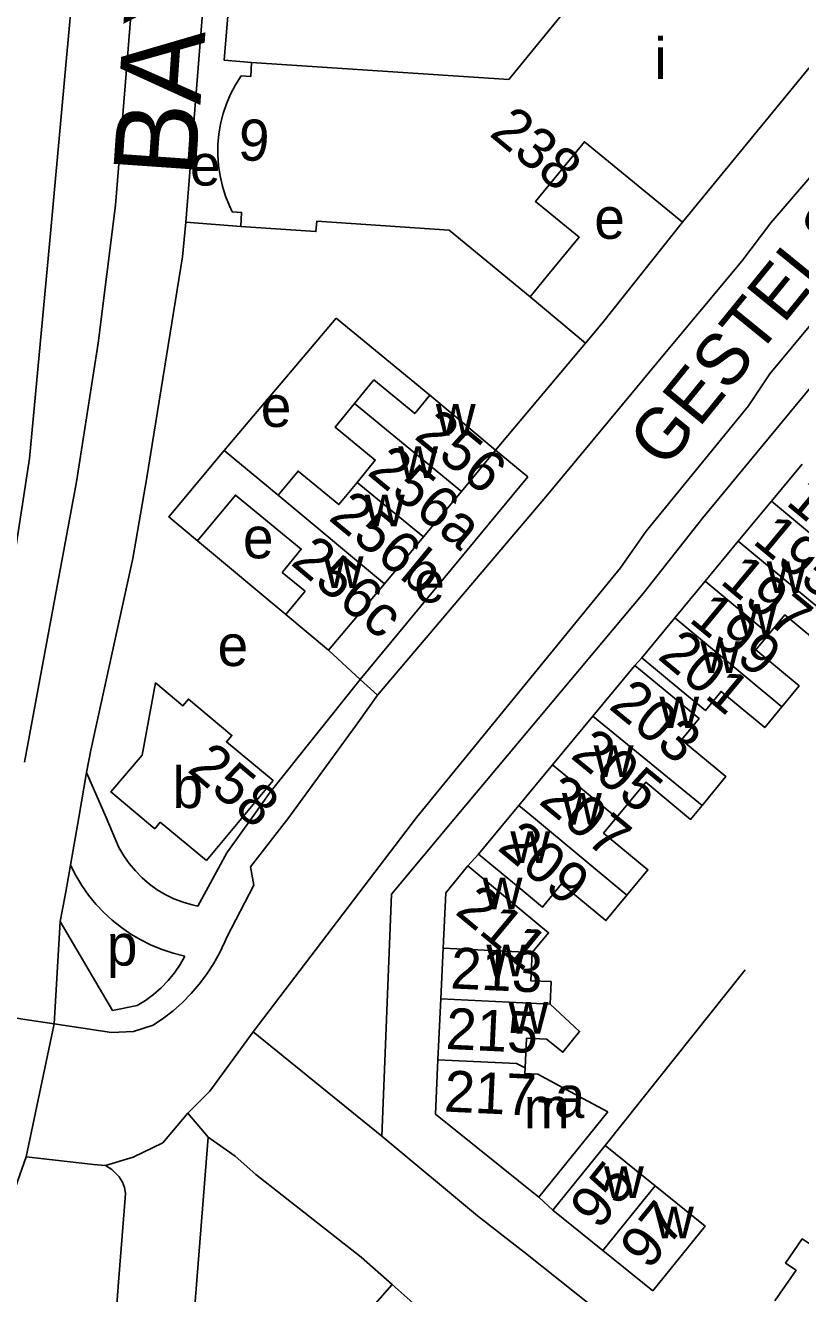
# Model space of a CAD drawing. Extents: x 159045 to 160918, y 380454 to 382516.
# Drawn here: x 160524.1 to 160599.4, y 381703.8 to 381826.9 of the extents above; entities that cross this region are included whole.
import ezdxf

# ---------------------------------------------------------------- set-up
doc = ezdxf.new("R2010")
doc.units = 0
for name, color, linetype in [('BLT_Basislijn', 7, 'Continuous'), ('BLT_Bebouwing', 7, 'Continuous'), ('BLT_Centroide', 7, 'Continuous'), ('BLT_Huisnummer', 7, 'Continuous'), ('BLT_Huisnummer_ tussenligend', 7, 'Continuous'), ('BLT_Huisnummer_reeks', 7, 'Continuous'), ('BLT_Onderverdeling_panden', 7, 'Continuous'), ('BLT_Straatnaam', 7, 'Continuous'), ('BLT_Straatnaam_hoofdweg', 7, 'Continuous'), ('BLT_Vlakafsluiter', 7, 'Continuous')]:
    doc.layers.add(name, color=color, linetype=linetype)

msp = doc.modelspace()

# ---------------------------------------------------------------- linework, layer by layer
at = {"layer": 'BLT_Basislijn'}
for p, q in [((160545.26, 381877.89), (160539.7, 381807.84)), ((160539.7, 381807.84), (160545.04, 381807.4)), ((160578.52, 381796.06), (160573.14, 381800.58)), ((160554.29, 381798.49), (160543.43, 381785.66)), ((160563.4, 381791.02), (160554.29, 381798.49)), ((160578.52, 381796.06), (160569.79, 381785.67)), ((160583.54, 381791.85), (160574.83, 381781.35)), ((160572.92, 381783.09), (160569.79, 381785.67)), ((160535.92, 381783.04), (160534.55, 381775.16)), ((160556.64, 381763.41), (160572.92, 381783.09)), ((160558.31, 381761.88), (160574.83, 381781.35)), ((160540.82, 381776.89), (160549.4, 381769.73)), ((160553.56, 381766.25), (160556.64, 381763.41)), ((160583.98, 381765.53), (160583.3, 381764.78)), ((160556.64, 381763.41), (160558.31, 381761.88)), ((160556.39, 381759.19), (160558.31, 381761.88)), ((160549.71, 381750), (160556.39, 381759.19)), ((160530.07, 381754.37), (160529.31, 381750)), ((160531.96, 381750), (160530.07, 381754.37)), ((160529.31, 381750), (160528.49, 381745.37)), ((160533.21, 381747.11), (160531.96, 381750)), ((160562.11, 381750), (160546.24, 381729.19)), ((160568.13, 381746.46), (160567.1, 381745.31)), ((160532.59, 381731.28), (160527.49, 381739.92)), ((160594.03, 381735.21), (160580.41, 381718.15)), ((160558.73, 381719.05), (160546.24, 381729.19)), ((160539.89, 381721.31), (160537.48, 381718.42)), ((160539.89, 381721.31), (160541.87, 381718.96)), ((160538.64, 381677.96), (160541.87, 381718.96)), ((160537.48, 381718.42), (160534.6, 381717.03)), ((160521.87, 381710.43), (160524.19, 381717.05)), ((160530.75, 381716.32), (160524.19, 381717.05)), ((160534.6, 381717.03), (160531.9, 381716.23)), ((160573.98, 381713.13), (160575.35, 381711.87)), ((160556.41, 381700.89), (160559.74, 381704.65))]:
    msp.add_line(p, q, dxfattribs=at)
for points in [[(160630.5, 381856.93), (160627.44, 381851.05), (160627.38, 381850.64), (160623.85, 381844.62), (160623.59, 381843.87), (160623.4, 381843.8), (160619.4, 381836.92), (160612.55, 381827.04), (160604.96, 381817.25), (160603.12, 381815.43), (160596.51, 381807.76), (160593.69, 381804.04), (160585.38, 381794.06), (160583.54, 381791.85)], [(160545.29, 381846.29), (160543.41, 381823.57), (160546.08, 381823.33)], [(160634.42, 381840.93), (160632, 381837.4), (160628.03, 381832.26), (160624.12, 381827.63), (160610.4, 381810.26), (160609.17, 381809.21), (160604.69, 381803.08), (160596.41, 381793.11), (160594.35, 381789.99), (160584.42, 381777.82), (160581.93, 381774.26), (160562.11, 381750)], [(160637.54, 381837.84), (160636.85, 381836.6), (160613.78, 381807.88), (160607.9, 381801.13), (160606.71, 381799.43), (160589.92, 381779.11), (160584.12, 381771.76), (160565.9, 381750)], [(160526.59, 381807.08), (160528.77, 381830.9)], [(160534.54, 381830.29), (160532.86, 381809.49), (160531.18, 381796.06), (160529.08, 381782.62)], [(160535.92, 381783.04), (160539.38, 381804.47), (160539.7, 381807.84)], [(160587.94, 381807.83), (160580.18, 381798.05), (160578.52, 381796.06)], [(160519.94, 381756.04), (160520.49, 381758.9), (160524.52, 381784.88), (160526.59, 381807.08)], [(160529.08, 381782.62), (160524.03, 381755.37)], [(160534.55, 381775.16), (160530.46, 381756.56), (160530.07, 381754.37)], [(160556.64, 381763.41), (160547.89, 381752.46), (160546.13, 381750)], [(160546.13, 381750), (160543.69, 381746.58), (160540.87, 381741.41)], [(160543.68, 381738.4), (160546.31, 381743.44), (160545.99, 381745.23), (160549.71, 381750)], [(160565.9, 381750), (160559.67, 381742.56), (160558.73, 381719.05)], [(160572.27, 381708.04), (160572.54, 381707.84), (160600.81, 381685.3), (160603.46, 381685.3), (160622.75, 381711.11), (160649.16, 381750)], [(160533.21, 381747.11), (160533.67, 381746.3), (160534.2, 381745.53), (160534.8, 381744.82), (160535.45, 381744.15), (160536.16, 381743.54), (160536.91, 381743), (160537.71, 381742.52), (160538.55, 381742.12), (160539.43, 381741.79), (160540.32, 381741.53), (160540.87, 381741.41)], [(160528.49, 381745.37), (160528.04, 381742.79), (160527.49, 381739.92)], [(160528.49, 381745.37), (160529.01, 381744.37), (160529.59, 381743.4), (160530.24, 381742.48), (160530.95, 381741.61), (160531.73, 381740.79), (160532.56, 381740.03), (160533.44, 381739.33), (160534.37, 381738.69), (160535.34, 381738.12), (160536.35, 381737.62), (160537.39, 381737.2), (160538.46, 381736.85), (160539.62, 381736.54)], [(160527.49, 381739.92), (160527.49, 381739.92), (160526.9, 381729.96)], [(160536.53, 381729.83), (160537.52, 381730.51), (160538.48, 381731.24), (160539.37, 381732.05), (160540.22, 381732.91), (160541, 381733.82), (160541.72, 381734.78), (160542.38, 381735.79), (160542.97, 381736.84), (160543.49, 381737.93), (160543.68, 381738.4)], [(160539.62, 381736.54), (160539.15, 381735.72), (160538.59, 381734.92), (160537.98, 381734.17), (160537.3, 381733.47), (160536.57, 381732.83), (160535.79, 381732.25), (160534.96, 381731.74), (160532.59, 381731.28)], [(160526.9, 381729.96), (160532.47, 381729.13), (160534.61, 381729.24), (160536.53, 381729.83)], [(160539.89, 381721.31), (160542.04, 381723.42), (160546.24, 381729.19)], [(160559.74, 381704.65), (160556.74, 381707.32), (160546.49, 381715.34), (160544.48, 381717.13), (160541.87, 381718.96)], [(160558.73, 381719.05), (160568.02, 381711.34), (160572.27, 381708.04)], [(160530.75, 381716.32), (160531.9, 381716.23)], [(160531.9, 381716.23), (160532.52, 381715.84), (160532.82, 381715.52), (160533.24, 381715.1), (160533.56, 381714.6), (160533.76, 381714.07), (160533.84, 381713.54), (160533.81, 381713.04)], [(160533.81, 381713.04), (160533.21, 381705.3), (160532.22, 381692.42), (160530.89, 381667.81), (160530.67, 381655.34), (160530.77, 381650.22), (160531.45, 381638.5), (160533.95, 381620.32), (160536.12, 381609.95)], [(160596.95, 381674.05), (160564.68, 381700.27), (160559.74, 381704.65)]]:
    msp.add_lwpolyline(points, dxfattribs=at)
at = {"layer": 'BLT_Bebouwing'}
for p, q in [((160543.43, 381785.66), (160548.67, 381781.3)), ((160566.46, 381781.68), (160569.79, 381785.67)), ((160599.55, 381784.31), (160596.58, 381780.73)), ((160562.77, 381777.26), (160566.46, 381781.68)), ((160596.58, 381780.73), (160593.35, 381776.84)), ((160558.98, 381772.71), (160562.77, 381777.26)), ((160593.35, 381776.84), (160590.13, 381772.96)), ((160551.28, 381771.98), (160549.05, 381773.81)), ((160553.56, 381766.25), (160558.98, 381772.71)), ((160590.13, 381772.96), (160587.18, 381769.4)), ((160549.4, 381769.73), (160551.28, 381771.98)), ((160553.56, 381766.25), (160549.4, 381769.73)), ((160587.18, 381769.4), (160583.98, 381765.53)), ((160583.3, 381764.78), (160579.23, 381759.86)), ((160579.23, 381759.86), (160575.32, 381755.14)), ((160575.32, 381755.14), (160572.03, 381751.17)), ((160572.03, 381751.17), (160571.07, 381750)), ((160536.69, 381748.92), (160537.22, 381749.56)), ((160537.22, 381749.56), (160541.71, 381745.82)), ((160571.07, 381750), (160568.13, 381746.46)), ((160564.69, 381737.31), (160564.46, 381732.39)), ((160564.46, 381732.39), (160564.18, 381726.49)), ((160580.41, 381718.15), (160575.35, 381711.87)), ((160580.41, 381718.15), (160585.27, 381714.24)), ((160575.35, 381711.87), (160580.21, 381707.96)), ((160580.21, 381707.96), (160585.07, 381704.04))]:
    msp.add_line(p, q, dxfattribs=at)
for points in [[(160578.66, 381830.96), (160571.06, 381821.68)], [(160605.3, 381829.37), (160603.62, 381826.95), (160587.94, 381807.83)], [(160546.08, 381823.33), (160546, 381821.98), (160545.07, 381822.03)], [(160571.06, 381821.68), (160546.08, 381823.33)], [(160545.07, 381822.03), (160544.53, 381821.17), (160544.05, 381820.27), (160543.65, 381819.33), (160543.33, 381818.37), (160543.08, 381817.38), (160542.91, 381816.38), (160542.82, 381815.36), (160542.81, 381814.34), (160542.88, 381813.33), (160543.02, 381812.32), (160543.25, 381811.33), (160543.55, 381810.36), (160543.93, 381809.41), (160544.21, 381808.84)], [(160574.83, 381802.64), (160577.89, 381806.36), (160573.65, 381809.84), (160578.41, 381815.64), (160587.94, 381807.83)], [(160544.21, 381808.84), (160545.12, 381808.77), (160545.04, 381807.4)], [(160545.04, 381807.4), (160552.34, 381806.92), (160552.42, 381807.92), (160565.26, 381807.05), (160573.14, 381800.58)], [(160573.14, 381800.58), (160574.83, 381802.64)], [(160556.09, 381790.21), (160557.97, 381792.5), (160561.93, 381789.24), (160563.4, 381791.02)], [(160556.33, 381782.56), (160558.1, 381784.72), (160554.2, 381787.93), (160556.09, 381790.21)], [(160569.79, 381785.67), (160565.95, 381788.88), (160563.4, 381791.02)], [(160540.82, 381776.89), (160538.04, 381779.22), (160543.43, 381785.66)], [(160548.67, 381781.3), (160550.6, 381783.65), (160554.55, 381780.4), (160556.33, 381782.56)], [(160549.05, 381773.81), (160550.91, 381776.08), (160544.52, 381781.33), (160540.82, 381776.89)], [(160605.8, 381766.49), (160603.8, 381764.13), (160601.81, 381765.78), (160602.12, 381766.16), (160597.87, 381769.68), (160596.32, 381767.81)], [(160596.32, 381767.81), (160595.05, 381766.29), (160599.27, 381762.79), (160597.59, 381760.77)], [(160583.98, 381765.53), (160587.82, 381762.34), (160590.16, 381760.4), (160591.69, 381762.25), (160595.92, 381758.74), (160597.59, 381760.77)], [(160589.85, 381751.19), (160592.15, 381753.98), (160587.84, 381757.55), (160589.55, 381759.61), (160587.15, 381761.59), (160583.3, 381764.78)], [(160541.71, 381745.82), (160548.18, 381753.59), (160543.66, 381757.35), (160544.18, 381757.98), (160539.95, 381761.51), (160539.42, 381760.86), (160536.77, 381763.08), (160535.45, 381756.06), (160532.43, 381752.49), (160536.69, 381748.92)], [(160581.52, 381750.01), (160584.36, 381753.44), (160588.72, 381749.83), (160589.85, 381751.19)], [(160582.54, 381742.47), (160584.58, 381744.93), (160580.27, 381748.5), (160581.52, 381750.01)], [(160568.13, 381746.46), (160571.98, 381743.27), (160574.34, 381741.31), (160576.2, 381743.57), (160580.5, 381740), (160582.54, 381742.47)], [(160567.1, 381745.31), (160564.94, 381742.7), (160564.69, 381737.31)], [(160573.35, 381736.91), (160574.93, 381738.82), (160570.95, 381742.12), (160567.1, 381745.31)], [(160573.35, 381736.91), (160573.19, 381734.16), (160575.18, 381734.07), (160575.08, 381731.89)], [(160575.08, 381731.89), (160577.94, 381729.23), (160576.32, 381727.21), (160574.74, 381728.47), (160572.77, 381728.57), (160572.64, 381725.69)], [(160564.18, 381726.49), (160563.94, 381721.21), (160573.98, 381713.13)], [(160572.64, 381725.69), (160572.61, 381725.15), (160573.87, 381725.09), (160577.82, 381722.95)], [(160580.67, 381721.44), (160577.12, 381717.02), (160573.98, 381713.13)], [(160585.27, 381714.24), (160590.13, 381710.33), (160587.93, 381707.59), (160586.16, 381705.4), (160585.07, 381704.04)], [(160600.54, 381708.43), (160599.57, 381709.09), (160597.95, 381706.74), (160598.96, 381706.04), (160596.91, 381703.08)]]:
    msp.add_lwpolyline(points, dxfattribs=at)
at = {"layer": 'BLT_Onderverdeling_panden'}
for p, q in [((160556.09, 381790.21), (160566.46, 381781.68)), ((160556.33, 381782.56), (160562.77, 381777.26)), ((160548.67, 381781.3), (160558.98, 381772.71)), ((160602.82, 381775.5), (160596.58, 381780.73)), ((160605.8, 381766.49), (160593.35, 381776.84)), ((160596.32, 381767.81), (160590.13, 381772.96)), ((160597.59, 381760.77), (160587.18, 381769.4)), ((160589.85, 381751.19), (160579.23, 381759.86)), ((160581.52, 381750.01), (160575.32, 381755.14)), ((160573.45, 381750), (160572.03, 381751.17)), ((160582.54, 381742.47), (160573.45, 381750)), ((160564.69, 381737.31), (160573.35, 381736.91)), ((160564.46, 381732.39), (160575.08, 381731.89)), ((160577.82, 381722.95), (160580.67, 381721.44)), ((160585.27, 381714.24), (160580.21, 381707.96))]:
    msp.add_line(p, q, dxfattribs=at)
msp.add_lwpolyline([(160564.18, 381726.49), (160571.8, 381726.13), (160572.64, 381725.69)], dxfattribs=at)
at = {"layer": 'BLT_Vlakafsluiter'}
msp.add_line((160526.9, 381729.96), (160524.19, 381717.05), dxfattribs=at)
msp.add_lwpolyline([(160513.26, 381732.37), (160516.57, 381731.78), (160523.66, 381730.45), (160526.9, 381729.96)], dxfattribs=at)

# ---------------------------------------------------------------- texts
at = {"layer": 'BLT_Centroide'}
for s, p in [('i', (160585.2, 381821.72)), ('e', (160540.09, 381811.38)), ('e', (160579.37, 381806.21)), ('e', (160546.98, 381787.94)), ('w', (160563.98, 381787.09)), ('w', (160560.33, 381782.98)), ('w', (160557.09, 381778.28)), ('e', (160545.25, 381775.18)), ('w', (160553.09, 381772.3)), ('e', (160561.88, 381770.9)), ('w', (160596.11, 381771.81)), ('w', (160593.23, 381767.66)), ('e', (160542.79, 381764.72)), ('w', (160589.67, 381764.06)), ('w', (160585.69, 381758.69)), ('w', (160579.31, 381753.95)), ('b', (160538.41, 381750.93)), ('w', (160576.23, 381749.33)), ('w', (160571.22, 381745.59)), ('w', (160568.52, 381741.09)), ('p', (160532.03, 381735.63)), ('w', (160568.89, 381734.59)), ('w', (160571.04, 381729.03)), ('m', (160572.52, 381719.81)), ('w', (160580.31, 381713.06)), ('w', (160585.17, 381709.14))]:
    msp.add_text(s, height=4, dxfattribs=at).set_placement(p)
at = {"layer": 'BLT_Huisnummer'}
for s, rotation, p in [('256', 320.5729, (160561.77, 381786.9)), ('256a', 320.5748, (160557.2, 381783.4)), ('256b', 320.5748, (160553.45, 381778.99)), ('195', 320.3333, (160594.63, 381776.72)), ('256c', 320.0376, (160549.78, 381774.65)), ('199', 320.3257, (160588.45, 381769.13)), ('203', 320.7662, (160580.66, 381760.67)), ('258', 319.7682, (160539.73, 381754.56)), ('207', 320.3886, (160573.86, 381751.44)), ('211', 320.3558, (160565.74, 381740.73)), ('213', 357.3206, (160565.35, 381733.42)), ('95', 51.1583, (160579.83, 381709.86)), ('97', 51.1583, (160584.69, 381705.97))]:
    msp.add_text(s, height=4, rotation=rotation, dxfattribs=at).set_placement(p)
at = {"layer": 'BLT_Huisnummer_ tussenligend'}
for s, rotation, p in [('193', 320.3134, (160597.86, 381780.47)), ('197', 320.3333, (160591.47, 381772.82)), ('201', 320.3257, (160585.4, 381765.51)), ('205', 320.7662, (160576.95, 381755.88)), ('209', 320.3886, (160569.85, 381746.95)), ('215', 357.3206, (160564.89, 381727.54))]:
    msp.add_text(s, height=4, rotation=rotation, dxfattribs=at).set_placement(p)
at = {"layer": 'BLT_Huisnummer_reeks'}
for s, rotation, p in [('238', 320.5729, (160569.07, 381816.3)), ('9', 356.2957, (160544.71, 381813.89)), ('217-a', 357.3232, (160564.73, 381721.46))]:
    msp.add_text(s, height=4, rotation=rotation, dxfattribs=at).set_placement(p)
at = {"layer": 'BLT_Straatnaam'}
msp.add_text('GESTELSESTRAAT', height=5, rotation=50.8707, dxfattribs=at).set_placement((160586.25, 381783.74))
at = {"layer": 'BLT_Straatnaam_hoofdweg'}
msp.add_text('BAYEUXLAAN', height=8, rotation=86.0424, dxfattribs=at).set_placement((160540.62, 381812.06))

doc.saveas('drawing.dxf')
